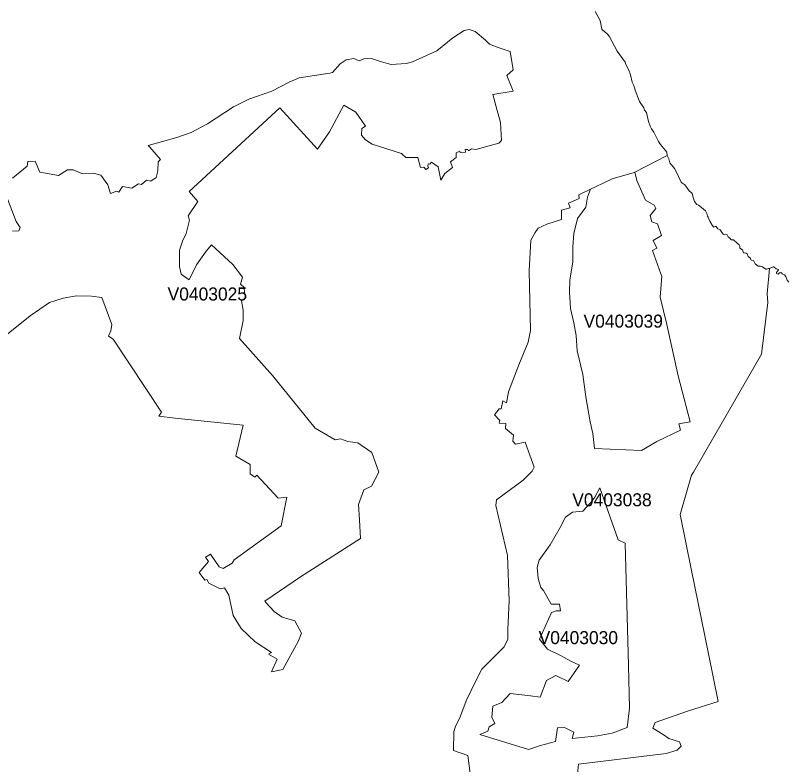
# Model space of a CAD drawing. Extents: x 369010 to 735936, y 6377141 to 6616555.
# Drawn here: x 414663 to 420601, y 6490450 to 6496204 of the extents above; entities that cross this region are included whole.
import ezdxf
from ezdxf.enums import TextEntityAlignment as Align

# ---------------------------------------------------------------- set-up
doc = ezdxf.new("R2010")
doc.units = 0
doc.header["$LTSCALE"] = 40
doc.layers.add('3', color=7, linetype='Continuous', lineweight=13)
doc.layers.add('4', color=7, linetype='Continuous')

msp = doc.modelspace()

# ---------------------------------------------------------------- linework, layer by layer
at = {"layer": '3'}
for points in [[(418244.5, 6491181.19), (418312.52, 6491249.7), (418417.62, 6491353.64), (418445.59, 6491413.72), (418444.93, 6491489.35), (418454.03, 6491707.65), (418441.45, 6492055.21), (418352.08, 6492439.18), (418358.04, 6492482.21), (418561.11, 6492634.15), (418630.29, 6492703.33), (418646.01, 6492733.94), (418577.33, 6492926.92), (418502.19, 6492910.04), (418483.99, 6492932.88), (418488.45, 6492979.22), (418425.56, 6493030.53), (418428.87, 6493069.75), (418376.74, 6493072.23), (418381.87, 6493093.09), (418342.81, 6493137.44), (418377.07, 6493183.62), (418393.29, 6493181.63), (418405.7, 6493243.7), (418434.5, 6493229.3), (418449.4, 6493312.22), (418529.83, 6493520.92), (418601.82, 6493695.36), (418617.71, 6493785.23), (418607.62, 6494243.67), (418620.03, 6494478.52), (418654.45, 6494535.95), (418678.78, 6494571.37), (418744.65, 6494601.49), (418858.02, 6494636.25), (418857.53, 6494709.57), (418922.24, 6494725.95), (418911.65, 6494763.19), (418991.59, 6494799.43), (418989.27, 6494826.58), (419080.79, 6494870.27), (419119.02, 6494888.64), (419246.79, 6494948.22), (419416.1, 6494998.7), (419420.57, 6495001.02), (419668.33, 6495128.29), (419664.69, 6495153.94), (419656.75, 6495166.85), (419618.02, 6495212.86), (419602.46, 6495235.21), (419566.55, 6495306.87), (419548.01, 6495333.02), (419537.42, 6495354.2), (419525.34, 6495390.12), (419508.95, 6495459.3), (419495.21, 6495476.68), (419489.42, 6495495.38), (419456.65, 6495542.71), (419422.56, 6495631.09), (419412.3, 6495666.34), (419399.88, 6495692.99), (419387.14, 6495748.93), (419375.06, 6495784.18), (419351.56, 6495828.37), (419345.1, 6495846.08), (419285.19, 6495930.99), (419222.46, 6496046.34), (419206.41, 6496063.72), (419174.96, 6496091.03), (419172.15, 6496091.19), (419167.19, 6496099.97), (419156.26, 6496152.93), (419150.14, 6496170.64), (419114.22, 6496233.69)], [(414639.16, 6494953.68), (414753.19, 6495047.86), (414757.33, 6495081.45), (414813.44, 6495086.25), (414850.01, 6494999.69), (414992.35, 6494974.54), (415063.18, 6495018.23), (415106.88, 6495018.4), (415171.92, 6494991.09), (415262.28, 6494993.57), (415317.56, 6494976.36), (415371.35, 6494902.54), (415393.86, 6494836.51), (415438.71, 6494855.38), (415457.74, 6494847.6), (415486.05, 6494890.13), (415556.88, 6494877.88), (415607.69, 6494909.83), (415631.86, 6494906.18), (415669.26, 6494938.29), (415703.02, 6494930.68), (415742.58, 6494959.64), (415756.81, 6495010.95), (415759.29, 6495079.96), (415777.66, 6495097.67), (415694.42, 6495192.84), (415682.83, 6495204.59), (415901.46, 6495266.82), (416013.18, 6495304.72), (416137.14, 6495372.58), (416336.9, 6495503.65), (416455.57, 6495561.91), (416630.67, 6495624.14), (416763.9, 6495691.34), (416842.35, 6495725.1), (417077.86, 6495760.68), (417096.73, 6495766.64), (417155.82, 6495833.34), (417203.65, 6495863.29), (417261.08, 6495873.39), (417301.79, 6495855.02), (417338.37, 6495872.07), (417389.18, 6495875.71), (417473.09, 6495848.56), (417549.05, 6495828.21), (417663.58, 6495835.82), (417711.74, 6495847.74), (417899.59, 6495932.64), (418022.06, 6496032.6), (418110.11, 6496089.37), (418148.84, 6496096.49), (418192.53, 6496080.44), (418271.81, 6496014.4), (418304.41, 6495982.95), (418370.62, 6495958.13), (418461.81, 6495928.67), (418486.63, 6495786.17), (418436.49, 6495742.48), (418486.3, 6495623.48), (418329.9, 6495596.83), (418355.06, 6495502.83), (418389.48, 6495383.33), (418395.28, 6495243.98), (418374.59, 6495223.95), (418199.15, 6495175.96), (418166.71, 6495180.09), (418142.88, 6495164.7), (418136.43, 6495175.96), (418117.56, 6495175.46)], [(417298.31, 6492446.63), (417337.87, 6492559.67), (417398.61, 6492587.64), (417454.72, 6492696.54), (417399.27, 6492846.49), (417291.53, 6492921.46), (417214.9, 6492930.23), (417159.46, 6492952.41), (417118.91, 6492943.97), (416964.82, 6493034.5), (416800.15, 6493235.92), (416637.29, 6493439.65), (416383.41, 6493723.99), (416411.88, 6493861.52), (416411.21, 6493939.14), (416399.96, 6494011.97), (416432.4, 6494037.95), (416421.31, 6494074.36), (416419.32, 6494113.59), (416390.03, 6494139.74), (416407.57, 6494193.19), (416332.76, 6494291.01), (416167.26, 6494442.44), (416128.2, 6494393.95), (416054.39, 6494288.19), (415997.78, 6494173.17), (415935.72, 6494216.2), (415923.31, 6494276.94), (415921.82, 6494401.56), (415945.98, 6494470.74), (415974.78, 6494529.33), (415988.85, 6494591.73), (415998.45, 6494631.28), (415990.17, 6494665.05), (416064.65, 6494775.44), (415996.79, 6494851.24), (416692.9, 6495495.71), (416981.54, 6495177.61), (417074.06, 6495309.52), (417185.28, 6495515.74), (417277.46, 6495461.95), (417351.28, 6495355.03), (417322.31, 6495336.66), (417320.66, 6495285.52), (417351.28, 6495250.1), (417401.59, 6495216.5), (417627.17, 6495144.35), (417659.94, 6495113.06), (417753.62, 6495112.07), (417774.3, 6495037.59), (417798.47, 6495039.91), (417813.86, 6495021.04), (417835.71, 6495034.12), (417829.25, 6495048.85), (417832.89, 6495065.4), (417844.64, 6495063.08), (417857.06, 6495077.15), (417910.51, 6495041.73), (417928.72, 6494938.95), (417960.66, 6494990.43), (418020.41, 6495036.93), (418003.36, 6495079.3), (418048.38, 6495114.06), (418048.38, 6495149.48), (418076.18, 6495161.23), (418078.5, 6495151.79), (418120.54, 6495155.27), (418117.56, 6495175.46), (418136.43, 6495175.96), (418142.88, 6495164.7), (418166.71, 6495180.09), (418199.15, 6495175.96), (418374.59, 6495223.95), (418395.28, 6495243.98), (418389.48, 6495383.33), (418355.06, 6495502.83), (418329.9, 6495596.83), (418486.3, 6495623.48), (418436.49, 6495742.48), (418486.63, 6495786.17), (418461.81, 6495928.67), (418370.62, 6495958.13), (418304.41, 6495982.95), (418271.81, 6496014.4), (418192.53, 6496080.44), (418148.84, 6496096.49), (418110.11, 6496089.37), (418022.06, 6496032.6), (417899.59, 6495932.64), (417711.74, 6495847.74), (417663.58, 6495835.82), (417549.05, 6495828.21), (417473.09, 6495848.56), (417389.18, 6495875.71), (417338.37, 6495872.07), (417301.79, 6495855.02), (417261.08, 6495873.39), (417203.65, 6495863.29), (417155.82, 6495833.34), (417096.73, 6495766.64)], [(417096.73, 6495766.64), (417077.86, 6495760.68), (416842.35, 6495725.1), (416763.9, 6495691.34), (416630.67, 6495624.14), (416455.57, 6495561.91), (416336.9, 6495503.65), (416137.14, 6495372.58), (416013.18, 6495304.72), (415901.46, 6495266.82), (415682.83, 6495204.59), (415694.42, 6495192.84), (415777.66, 6495097.67), (415759.29, 6495079.96), (415756.81, 6495010.95), (415742.58, 6494959.64), (415703.02, 6494930.68), (415669.26, 6494938.29), (415631.86, 6494906.18), (415607.69, 6494909.83), (415556.88, 6494877.88), (415486.05, 6494890.13), (415457.74, 6494847.6), (415438.71, 6494855.38), (415393.86, 6494836.51), (415371.35, 6494902.54), (415317.56, 6494976.36), (415262.28, 6494993.57), (415171.92, 6494991.09), (415106.88, 6495018.4), (415063.18, 6495018.23), (414992.35, 6494974.54), (414850.01, 6494999.69), (414813.44, 6495086.25), (414757.33, 6495081.45)], [(418117.56, 6495175.46), (418120.54, 6495155.27), (418078.5, 6495151.79), (418076.18, 6495161.23), (418048.38, 6495149.48), (418048.38, 6495114.06), (418003.36, 6495079.3), (418020.41, 6495036.93), (417960.66, 6494990.43), (417928.72, 6494938.95), (417910.51, 6495041.73), (417857.06, 6495077.15), (417844.64, 6495063.08), (417832.89, 6495065.4), (417829.25, 6495048.85), (417835.71, 6495034.12), (417813.86, 6495021.04), (417798.47, 6495039.91), (417774.3, 6495037.59), (417753.62, 6495112.07), (417659.94, 6495113.06), (417627.17, 6495144.35), (417401.59, 6495216.5), (417351.28, 6495250.1), (417320.66, 6495285.52), (417322.31, 6495336.66), (417351.28, 6495355.03), (417277.46, 6495461.95), (417185.28, 6495515.74), (417074.06, 6495309.52), (416981.54, 6495177.61), (416692.9, 6495495.71), (415996.79, 6494851.24), (416064.65, 6494775.44), (415990.17, 6494665.05)], [(419668.33, 6495128.29), (419420.57, 6495001.02), (419434.64, 6494937.47), (419502.83, 6494785.2), (419569.03, 6494746.8), (419580.61, 6494720.65), (419536.92, 6494667.53), (419551.16, 6494619.2), (419593.69, 6494603.81), (419625.47, 6494514.6), (419561.75, 6494474.55), (419589.06, 6494417.78), (419556.45, 6494398.25), (419620.17, 6494218.85), (419627.95, 6494201.3), (419614.05, 6494039.61), (419666.02, 6493829.25), (419753.9, 6493435.02), (419845.26, 6493081.67), (419759.03, 6493066.11), (419770.78, 6493017.78), (419590.21, 6492931.89), (419470.55, 6492862.87), (419111.41, 6492876.61), (419097.34, 6492991.97), (419075.83, 6493081.34), (419043.22, 6493275.64), (419019.72, 6493447.27), (418976.19, 6493627), (418970.4, 6493746.99), (418951.87, 6493844.31), (418926.38, 6493952.55), (418918.43, 6494077.84), (418921.25, 6494173.17), (418942.76, 6494309.54), (418944.91, 6494427.71), (418950.87, 6494530.16), (418978.68, 6494645.35), (419042.56, 6494732.07), (419056.13, 6494807.54), (419080.79, 6494870.27), (418989.27, 6494826.58), (418991.59, 6494799.43), (418911.65, 6494763.19), (418922.24, 6494725.95), (418857.53, 6494709.57), (418858.02, 6494636.25), (418744.65, 6494601.49), (418678.78, 6494571.37), (418654.45, 6494535.95), (418620.03, 6494478.52), (418607.62, 6494243.67), (418617.71, 6493785.23), (418601.82, 6493695.36), (418529.83, 6493520.92), (418449.4, 6493312.22), (418434.5, 6493229.3), (418405.7, 6493243.7), (418393.29, 6493181.63), (418377.07, 6493183.62), (418342.81, 6493137.44), (418381.87, 6493093.09), (418376.74, 6493072.23), (418428.87, 6493069.75), (418425.56, 6493030.53), (418488.45, 6492979.22), (418483.99, 6492932.88), (418502.19, 6492910.04), (418577.33, 6492926.92), (418646.01, 6492733.94), (418630.29, 6492703.33), (418561.11, 6492634.15), (418358.04, 6492482.21), (418352.08, 6492439.18), (418441.45, 6492055.21), (418454.03, 6491707.65), (418444.93, 6491489.35), (418445.59, 6491413.72), (418417.62, 6491353.64), (418312.52, 6491249.7), (418244.5, 6491181.19), (418200.15, 6491098.93), (418125.01, 6490938.23), (418076.02, 6490808.97), (418041.76, 6490745.58), (418028.68, 6490701.89), (418026.7, 6490558.89), (418137.42, 6490518.34), (418216.7, 6489912.43)], [(418988.28, 6490453.3), (419661.55, 6490533.57), (419744.96, 6490559.39), (419777.07, 6490591.99), (419763.33, 6490625.26), (419681.08, 6490650.75), (419638.71, 6490680.87), (419557.28, 6490729.03), (419575.65, 6490772.72), (419831.85, 6490862.09), (420059.25, 6490934.92), (419984.94, 6491299.03), (419852.7, 6491954.26), (419769.29, 6492370.83), (419856.34, 6492673.54), (419869.42, 6492695.71), (420208.54, 6493281.1), (420391.92, 6493601.19), (420442.89, 6493998.23), (420436.44, 6494066.25), (420455.47, 6494259.73), (420450.01, 6494263.04), (420433.29, 6494254.6), (420425.18, 6494255.59), (420399.69, 6494273.96), (420384.14, 6494277.77), (420367.75, 6494279.09), (420345.57, 6494295.14), (420330.51, 6494321.79), (420316.78, 6494323.78), (420310.65, 6494327.42), (420308.01, 6494340.16), (420290.63, 6494352.57), (420281.86, 6494373.43), (420275.07, 6494379.05), (420260.34, 6494379.72), (420255.71, 6494381.7), (420248.26, 6494404.87), (420226.74, 6494415.96), (420225.75, 6494432.84), (420221.78, 6494443.6), (420205.39, 6494454.69), (420179.08, 6494481.83), (420161.04, 6494480.18), (420150.61, 6494493.75), (420136.05, 6494504.51), (420131.08, 6494513.77), (420128.76, 6494519.9), (420120.99, 6494521.39), (420109.23, 6494519.57), (420097.81, 6494523.71), (420086.4, 6494541.74), (420074.48, 6494556.97), (420070.01, 6494560.61), (420057.43, 6494564.42), (420045.68, 6494583.29), (420041.87, 6494585.27), (420032.94, 6494579.98), (420027.81, 6494579.15), (420023.5, 6494581.8), (420013.57, 6494594.21), (419996.2, 6494624.99), (419988.75, 6494641.05), (419987.09, 6494650.98), (419984.28, 6494655.94), (419977.66, 6494663.39), (419973.19, 6494682.75), (419964.09, 6494703.11), (419933.14, 6494729.59), (419910.13, 6494746.14), (419896.73, 6494752.76), (419879.35, 6494775.11), (419869.42, 6494798.11), (419859.99, 6494836.18), (419852.87, 6494844.95), (419837.48, 6494857.36), (419805.37, 6494902.05), (419782.2, 6494917.44), (419776.9, 6494923.56), (419735.69, 6495009.62), (419724.44, 6495027.5), (419689.02, 6495072.68), (419682.23, 6495103.3), (419668.5, 6495127.46), (419668.33, 6495128.29)], [(414757.33, 6495081.45), (414753.19, 6495047.86), (414639.16, 6494953.68)], [(414640.82, 6494547.21), (414689.81, 6494550.85), (414699.57, 6494575.67), (414668.62, 6494621.02), (414588.35, 6494829.39)], [(414588.35, 6494829.39), (414668.62, 6494621.02), (414699.57, 6494575.67), (414689.81, 6494550.85), (414640.82, 6494547.21)], [(415990.17, 6494665.05), (415998.45, 6494631.28), (415988.85, 6494591.73), (415974.78, 6494529.33), (415945.98, 6494470.74), (415921.82, 6494401.56), (415923.31, 6494276.94), (415935.72, 6494216.2), (415997.78, 6494173.17), (416054.39, 6494288.19), (416128.2, 6494393.95), (416167.26, 6494442.44), (416332.76, 6494291.01), (416407.57, 6494193.19), (416390.03, 6494139.74), (416419.32, 6494113.59), (416421.31, 6494074.36), (416432.4, 6494037.95), (416399.96, 6494011.97), (416411.21, 6493939.14), (416411.88, 6493861.52), (416383.41, 6493723.99), (416637.29, 6493439.65), (416800.15, 6493235.92), (416964.82, 6493034.5), (417118.91, 6492943.97), (417159.46, 6492952.41), (417214.9, 6492930.23), (417291.53, 6492921.46), (417399.27, 6492846.49), (417454.72, 6492696.54), (417398.61, 6492587.64), (417337.87, 6492559.67), (417298.31, 6492446.63), (417304.11, 6492330.45), (417312.71, 6492186.62), (416851.45, 6491891.53), (416577.54, 6491705.5), (416587.31, 6491691.27), (416650.2, 6491624.74), (416710.94, 6491582.37), (416807.93, 6491553.57), (416860.72, 6491459.56), (416837.39, 6491400.31), (416717.23, 6491180.52), (416629.68, 6491162.98), (416674.03, 6491260.13), (416606.18, 6491296.71), (416628.35, 6491311.11), (416504.23, 6491392.87), (416395.66, 6491493.66), (416334.25, 6491594.12), (416300.82, 6491752.18), (416268.22, 6491807.62), (416234.29, 6491798.52), (416148.72, 6491843.04), (416133.83, 6491872.5), (416116.12, 6491866.54), (416073.09, 6491923.97), (416146.24, 6492009.86), (416121.42, 6492042.63), (416161.14, 6492065.47), (416227.17, 6491968.82), (416257.46, 6491954.59), (416326.64, 6491997.62), (416342.36, 6492021.12), (416704.49, 6492284.77), (416747.02, 6492503.56), (416681.48, 6492496.45), (416516.14, 6492671.88), (416500.42, 6492658.14), (416466.66, 6492683.47), (416464.17, 6492755.13), (416354.61, 6492818.52), (416412.87, 6493056.35), (415890.54, 6493111.29), (415764.59, 6493125.53), (415784.78, 6493156.31), (415412.73, 6493717.87), (415376.81, 6493740.04), (415394.52, 6493781.92), (415402.14, 6493829.25), (415327, 6494037.29), (415246.89, 6494047.55), (415130.38, 6494050.53), (415029.92, 6494032.82), (414923.83, 6493999.06), (414775.37, 6493896.11), (414460.58, 6493647.2)], [(420602.11, 6494155.29), (420590.35, 6494171.68), (420580.26, 6494200.14), (420570.16, 6494211.56), (420551.96, 6494219.01), (420550.63, 6494222.98), (420541.7, 6494229.77), (420530.94, 6494226.46), (420521.84, 6494217.36), (420508.43, 6494221.66), (420507.11, 6494229.44), (420524.82, 6494249.13), (420524.15, 6494252.28), (420506.78, 6494257.91), (420486.58, 6494272.97), (420481.95, 6494272.97), (420455.63, 6494259.56), (420455.47, 6494259.73), (420436.44, 6494066.25), (420442.89, 6493998.23), (420391.92, 6493601.19), (420208.54, 6493281.1), (419869.42, 6492695.71), (419856.34, 6492673.54), (419769.29, 6492370.83), (419852.7, 6491954.26), (419984.94, 6491299.03), (420059.25, 6490934.92), (419831.85, 6490862.09), (419575.65, 6490772.72), (419557.28, 6490729.03), (419638.71, 6490680.87), (419681.08, 6490650.75), (419763.33, 6490625.26), (419777.07, 6490591.99), (419744.96, 6490559.39), (419661.55, 6490533.57), (418988.28, 6490453.3), (418979.01, 6490376.01)], [(414460.58, 6493647.2), (414775.37, 6493896.11), (414923.83, 6493999.06), (415029.92, 6494032.82), (415130.38, 6494050.53), (415246.89, 6494047.55), (415327, 6494037.29), (415402.14, 6493829.25), (415394.52, 6493781.92), (415376.81, 6493740.04), (415412.73, 6493717.87), (415784.78, 6493156.31), (415764.59, 6493125.53), (415890.54, 6493111.29), (416412.87, 6493056.35), (416354.61, 6492818.52), (416464.17, 6492755.13), (416466.66, 6492683.47), (416500.42, 6492658.14), (416516.14, 6492671.88), (416681.48, 6492496.45), (416747.02, 6492503.56), (416704.49, 6492284.77), (416342.36, 6492021.12), (416326.64, 6491997.62), (416257.46, 6491954.59), (416227.17, 6491968.82), (416161.14, 6492065.47), (416121.42, 6492042.63), (416146.24, 6492009.86), (416073.09, 6491923.97), (416116.12, 6491866.54), (416133.83, 6491872.5), (416148.72, 6491843.04), (416234.29, 6491798.52), (416268.22, 6491807.62), (416300.82, 6491752.18), (416334.25, 6491594.12), (416395.66, 6491493.66), (416504.23, 6491392.87), (416628.35, 6491311.11), (416606.18, 6491296.71), (416674.03, 6491260.13), (416629.68, 6491162.98), (416717.23, 6491180.52), (416837.39, 6491400.31), (416860.72, 6491459.56), (416807.93, 6491553.57), (416710.94, 6491582.37), (416650.2, 6491624.74), (416587.31, 6491691.27), (416577.54, 6491705.5), (416851.45, 6491891.53), (417312.71, 6492186.62), (417304.11, 6492330.45), (417298.31, 6492446.63)], [(418216.7, 6489912.43), (418137.42, 6490518.34), (418026.7, 6490558.89), (418028.68, 6490701.89), (418041.76, 6490745.58), (418076.02, 6490808.97), (418125.01, 6490938.23), (418200.15, 6491098.93), (418244.5, 6491181.19)], [(418979.01, 6490376.01), (418988.28, 6490453.3)]]:
    msp.add_lwpolyline(points, dxfattribs=at)
for points in [[(419420.57, 6495001.02), (419416.1, 6494998.7), (419246.79, 6494948.22), (419119.02, 6494888.64), (419080.79, 6494870.27), (419056.13, 6494807.54), (419042.56, 6494732.07), (418978.68, 6494645.35), (418950.87, 6494530.16), (418944.91, 6494427.71), (418942.76, 6494309.54), (418921.25, 6494173.17), (418918.43, 6494077.84), (418926.38, 6493952.55), (418951.87, 6493844.31), (418970.4, 6493746.99), (418976.19, 6493627), (419019.72, 6493447.27), (419043.22, 6493275.64), (419075.83, 6493081.34), (419097.34, 6492991.97), (419111.41, 6492876.61), (419470.55, 6492862.87), (419590.21, 6492931.89), (419770.78, 6493017.78), (419759.03, 6493066.11), (419845.26, 6493081.67), (419753.9, 6493435.02), (419666.02, 6493829.25), (419614.05, 6494039.61), (419627.95, 6494201.3), (419620.17, 6494218.85), (419556.45, 6494398.25), (419589.06, 6494417.78), (419561.75, 6494474.55), (419625.47, 6494514.6), (419593.69, 6494603.81), (419551.16, 6494619.2), (419536.92, 6494667.53), (419580.61, 6494720.65), (419569.03, 6494746.8), (419502.83, 6494785.2), (419434.64, 6494937.47)], [(419150.3, 6492575.23), (419113.89, 6492502.57), (419081.95, 6492462.85), (419021.21, 6492396.81), (418941.77, 6492387.71), (418887.65, 6492349.81), (418845.28, 6492270.2), (418769.31, 6492138.46), (418685.73, 6492020.29), (418670.18, 6491964.02), (418676.3, 6491878.45), (418697.32, 6491809.94), (418718.84, 6491787.1), (418777.76, 6491681.84), (418840.98, 6491681.84), (418849.58, 6491631.69), (418814.99, 6491631.69), (418780.4, 6491616.63), (418688.38, 6491411.9), (418749.78, 6491335.6), (418849.09, 6491286.45), (418928.2, 6491243.25), (418996.22, 6491212.3), (418908.01, 6491088.34), (418814, 6491133.36), (418741.18, 6491095.12), (418694.01, 6490967.19), (418619.7, 6490976.95), (418463.3, 6490995.66), (418398.75, 6490926.48), (418329.74, 6490898.17), (418321.13, 6490814.59), (418344.96, 6490764.78), (418301.43, 6490739.62), (418290.35, 6490705.03), (418230.27, 6490681.53), (418603.98, 6490565.35), (418694.67, 6490596.96), (418809.53, 6490625.59), (418826.58, 6490730.52), (418878.88, 6490733.17), (418951.2, 6490697.25), (418937.63, 6490649.59), (419132.43, 6490670.77), (419246.63, 6490690.96), (419360.99, 6490733.17), (419378.53, 6490882.62), (419371.25, 6491211.64), (419344.61, 6492151.21), (419291.81, 6492176.53)], [(419150.3, 6492575.23), (419291.81, 6492176.53), (419344.61, 6492151.21), (419371.25, 6491211.64), (419378.53, 6490882.62), (419360.99, 6490733.17), (419246.63, 6490690.96), (419132.43, 6490670.77), (418937.63, 6490649.59), (418951.2, 6490697.25), (418878.88, 6490733.17), (418826.58, 6490730.52), (418809.53, 6490625.59), (418694.67, 6490596.96), (418603.98, 6490565.35), (418230.27, 6490681.53), (418290.35, 6490705.03), (418301.43, 6490739.62), (418344.96, 6490764.78), (418321.13, 6490814.59), (418329.74, 6490898.17), (418398.75, 6490926.48), (418463.3, 6490995.66), (418619.7, 6490976.95), (418694.01, 6490967.19), (418741.18, 6491095.12), (418814, 6491133.36), (418908.01, 6491088.34), (418996.22, 6491212.3), (418928.2, 6491243.25), (418849.09, 6491286.45), (418749.78, 6491335.6), (418688.38, 6491411.9), (418780.4, 6491616.63), (418814.99, 6491631.69), (418849.58, 6491631.69), (418840.98, 6491681.84), (418777.76, 6491681.84), (418718.84, 6491787.1), (418697.32, 6491809.94), (418676.3, 6491878.45), (418670.18, 6491964.02), (418685.73, 6492020.29), (418769.31, 6492138.46), (418845.28, 6492270.2), (418887.65, 6492349.81), (418941.77, 6492387.71), (419021.21, 6492396.81), (419081.95, 6492462.85), (419113.89, 6492502.57)]]:
    msp.add_lwpolyline(points, close=True, dxfattribs=at)

# ---------------------------------------------------------------- texts
at = {"layer": '4'}
for s, p in [('V0403025', (416136.25, 6494014.73)), ('V0403039', (419330.88, 6493806.06)), ('V0403038', (419244.54, 6492433.62)), ('V0403030', (418986.08, 6491374.8))]:
    msp.add_text(s, height=100, dxfattribs=at).set_placement(p, align=Align.CENTER)

doc.saveas('drawing.dxf')
